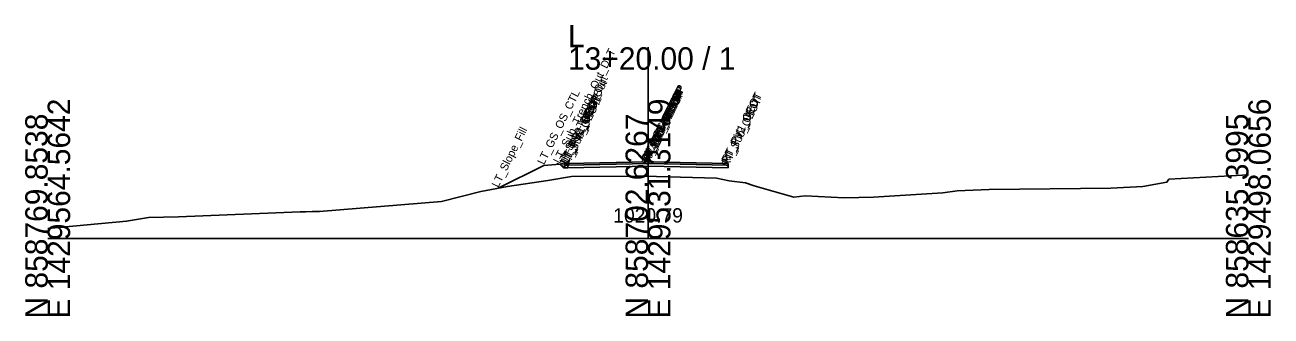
# Model space of a CAD drawing. Extents: x -26 to 2303, y -10 to 19558.
# Drawn here: x 1147.2 to 1302.8, y 7990.3 to 8026.7 of the extents above; entities that cross this region are included whole.
import ezdxf

# ---------------------------------------------------------------- set-up
doc = ezdxf.new("R2010")
doc.units = 0
for name, color, linetype in [('Default', 7, 'Continuous'), ('Exist Cross Section Cell', 7, 'Continuous'), ('Exist XS Center Line Elevation Label', 7, 'Continuous'), ('Exist XS Ground Line', 7, 'Continuous'), ('Prop CMT Pvmt Course 1', 7, 'Continuous'), ('Prop CMT Pvmt Course 2', 7, 'Continuous'), ('Prop CMT Pvmt Surface', 7, 'Continuous'), ('Prop CMT Pvmt Surface Shoulder', 7, 'Continuous'), ('Prop CMT Shld Paved Course 1', 7, 'Continuous'), ('Prop CMT Shld Paved Course 2', 7, 'Continuous'), ('Prop CMT Slope Grass', 7, 'Continuous'), ('Prop CMT Subgrade Earthwork', 7, 'Continuous'), ('Prop XS Dump Level', 7, 'Continuous')]:
    doc.layers.add(name, color=color, linetype=linetype)

msp = doc.modelspace()

# ---------------------------------------------------------------- linework, layer by layer
at = {"layer": 'Exist Cross Section Cell'}
for p, q in [((1225, 8000), (1225, 8023.89)), ((1150, 8000), (1225, 8000)), ((1225, 8000), (1300, 8000))]:
    msp.add_line(p, q, dxfattribs=at)
at = {"layer": 'Exist XS Ground Line'}
msp.add_lwpolyline([(1150, 8001.26), (1159.86, 8002.15), (1162.61, 8002.61), (1166.33, 8002.72), (1181.53, 8003.33), (1182.19, 8003.34), (1183.04, 8003.37), (1183.98, 8003.39), (1199.19, 8004.62), (1204.1, 8005.86), (1207.43, 8006.51), (1212.49, 8007.25), (1215.45, 8007.75), (1223.4, 8007.8), (1224.55, 8007.8), (1225, 8007.79), (1226.05, 8007.75), (1233.56, 8007.53), (1235.12, 8007.22), (1237.19, 8006.96), (1238.26, 8006.58), (1243.21, 8005.18), (1244.65, 8005.35), (1249.5, 8005.1), (1253.16, 8005.17), (1261.82, 8005.7), (1263.61, 8005.94), (1267.62, 8006.14), (1282.82, 8006.31), (1286.81, 8006.51), (1289.83, 8007.04), (1290.08, 8007.41), (1297.76, 8007.83), (1300, 8007.96)], dxfattribs=at)
at = {"layer": 'Prop CMT Pvmt Course 1'}
for points in [[(1225, 8009.58), (1215, 8009.38)], [(1215, 8009.38), (1215, 8009.17)], [(1215, 8009.17), (1225, 8009.37)], [(1225, 8009.37), (1225, 8009.58)], [(1225, 8009.58), (1235, 8009.38)], [(1225, 8009.37), (1225, 8009.58)], [(1235, 8009.17), (1225, 8009.37)], [(1235, 8009.38), (1235, 8009.17)]]:
    msp.add_lwpolyline(points, dxfattribs=at)
msp.add_lwpolyline([(1225, 8009.37), (1225, 8009.45), (1225, 8009.45), (1225, 8009.37)], close=True, dxfattribs=at)
msp.add_lwpolyline([(1225, 8009.37), (1225, 8009.45), (1225, 8009.45), (1225, 8009.37)], close=True, dxfattribs=at)
at = {"layer": 'Prop CMT Pvmt Course 2'}
for points in [[(1225, 8009.37), (1215, 8009.17)], [(1215, 8009.17), (1215, 8008.84)], [(1215, 8008.84), (1225, 8009.04)], [(1225, 8009.04), (1225, 8009.37)], [(1225, 8009.04), (1225, 8009.37)], [(1225, 8009.37), (1235, 8009.17)], [(1235, 8008.84), (1225, 8009.04)], [(1235, 8009.17), (1235, 8008.84)]]:
    msp.add_lwpolyline(points, dxfattribs=at)
at = {"layer": 'Prop CMT Pvmt Surface'}
for points in [[(1225, 8009.58), (1215, 8009.38)], [(1225, 8009.58), (1235, 8009.38)]]:
    msp.add_lwpolyline(points, dxfattribs=at)
at = {"layer": 'Prop CMT Pvmt Surface Shoulder'}
msp.add_lwpolyline([(1215, 8009.38), (1215, 8009.38)], dxfattribs=at)
at = {"layer": 'Prop CMT Shld Paved Course 1'}
for points in [[(1215, 8009.38), (1214.79, 8009.17)], [(1214.79, 8009.17), (1215, 8009.17)], [(1215, 8009.38), (1215, 8009.38)], [(1215, 8009.17), (1215, 8009.38)]]:
    msp.add_lwpolyline(points, dxfattribs=at)
at = {"layer": 'Prop CMT Shld Paved Course 2'}
for points in [[(1214.79, 8009.17), (1214.45, 8008.83)], [(1214.45, 8008.83), (1215, 8008.84)], [(1215, 8009.17), (1214.79, 8009.17)], [(1214.79, 8009.17), (1214.79, 8009.17)], [(1215, 8008.84), (1215, 8009.17)]]:
    msp.add_lwpolyline(points, dxfattribs=at)
at = {"layer": 'Prop CMT Slope Grass'}
msp.add_lwpolyline([(1215, 8009.38), (1212, 8009.14), (1206.3, 8006.29)], dxfattribs=at)
at = {"layer": 'Prop CMT Subgrade Earthwork'}
for points in [[(1214.45, 8008.83), (1213.98, 8009.3)], [(1215, 8008.84), (1214.45, 8008.83)], [(1225, 8009.04), (1215, 8008.84)], [(1225, 8009.04), (1235, 8008.84)]]:
    msp.add_lwpolyline(points, dxfattribs=at)

# ---------------------------------------------------------------- texts
at = {"layer": 'Default'}
msp.add_text('-', height=0.0001, dxfattribs=at).set_placement((1150, 8000))
at = {"layer": 'Exist Cross Section Cell'}
for s, p in [('L', (1215, 8023.89)), ('13+20.00 / 1', (1215, 8021.09))]:
    msp.add_text(s, height=2.8, dxfattribs=at).set_placement(p)
for s, p in [('E 1429564.5642', (1152.8, 7990)), ('E 1429531.3149', (1227.8, 7990)), ('E 1429498.0656', (1302.8, 7990)), ('N 858769.8538', (1150, 7990)), ('N 858702.6267', (1225, 7990)), ('N 858635.3995', (1300, 7990))]:
    msp.add_text(s, height=2.8, rotation=90, dxfattribs=at).set_placement(p)
at = {"layer": 'Exist XS Center Line Elevation Label'}
msp.add_text('1020.79', height=1.8, dxfattribs=at).set_placement((1220.66, 8001.99))
at = {"layer": 'Prop XS Dump Level'}
for s, p in [('LT_Sub_Trench_Out_DLT', (1213.98, 8009.3)), ('LT_Sub_Trench_Out', (1214.45, 8008.83)), ('LT_PS2_Shelf_Out', (1214.79, 8009.17)), ('RT_PV1_OEEOP', (1225, 8009.45)), ('LT_GS_OS_CTL', (1212, 8009.14)), ('LT_PS2_OEOP', (1214.79, 8009.17)), ('LT_PV1_OEOT', (1215, 8009.38)), ('LT_PS1_OEOP', (1215, 8009.38)), ('LT_PV2_OEOT', (1215, 8009.17)), ('RT_PV2_OEEOP', (1225, 8009.37)), ('LT_PV1_OEEOP', (1225, 8009.45)), ('LT_PV2_OEEOP', (1225, 8009.37)), ('RT_Sub_OEEOP', (1225, 8009.04)), ('RT_PV1_IEEOP', (1225, 8009.45)), ('RT_PV2_IEEOP', (1225, 8009.37)), ('LT_Sub_OEEOP', (1225, 8009.04)), ('LT_PV1_IEEOP', (1225, 8009.45)), ('LT_PV2_IEEOP', (1225, 8009.37)), ('RT_PV1_OEOT', (1235, 8009.38)), ('RT_PV2_OEOT', (1235, 8009.17)), ('RT_Sub_OEOT', (1235, 8008.84)), ('LT_Sub_OEOT', (1215, 8008.84)), ('PV1_PGL', (1225, 8009.58)), ('PV2_PGL', (1225, 8009.37)), ('LT_Slope_Fill', (1206.3, 8006.29))]:
    msp.add_text(s, height=1, rotation=63.5833, dxfattribs=at).set_placement(p)

doc.saveas('drawing.dxf')
